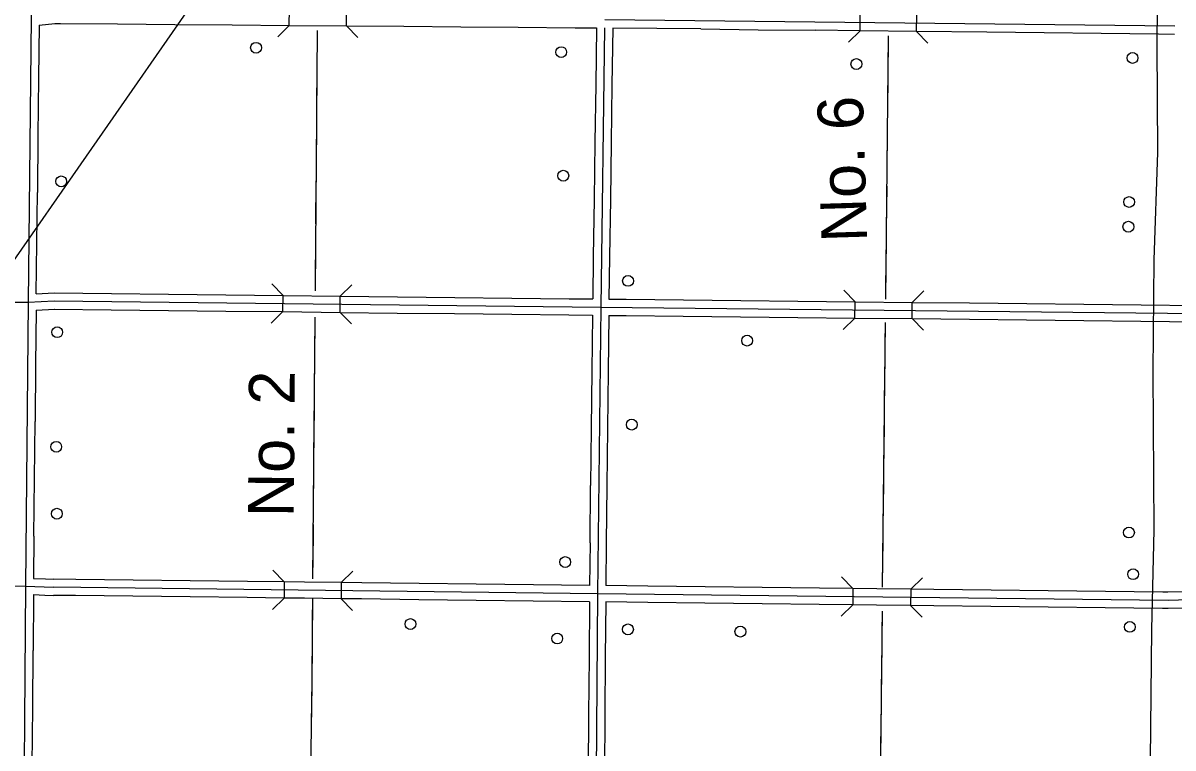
# Model space of a CAD drawing. Extents: x -4306 to 3843, y 131 to 8053.
# Drawn here: x -1949 to -251, y 879 to 1950 of the extents above; entities that cross this region are included whole.
import ezdxf

# ---------------------------------------------------------------- set-up
doc = ezdxf.new("R2010")
doc.units = 0
for name, color, linetype in [('10', 7, 'Continuous'), ('31', 7, 'Continuous'), ('32', 7, 'Continuous'), ('38', 7, 'Continuous'), ('43', 7, 'Continuous'), ('56', 7, 'Continuous'), ('R_No Plot', 7, 'Continuous')]:
    doc.layers.add(name, color=color, linetype=linetype)

msp = doc.modelspace()

# ---------------------------------------------------------------- linework, layer by layer
at = {"layer": '10'}
msp.add_lwpolyline([(-314.4, 293.8), (-314.5, 305.1), (-312.3, 441.3), (-305.4, 600.9), (-302, 628.3), (-293.8, 664.7), (-283.6, 735.2), (-284.1, 861.9), (-282.2, 1054.1), (-278.9, 1201.3), (-280.3, 1434.8), (-278.7, 1599.9), (-273.4, 1758.6), (-274.2, 1917.6), (-271, 2305.4), (-270.3, 2716.6), (-269.9, 2753.7)], dxfattribs=at)
at = {"layer": '31'}
for p, q in [((-713.1, 1938.1), (-712.8, 1962.1)), ((-629.6, 1937.2), (-629.3, 1961.2)), ((-948.3, 1940.8), (-1078.4, 1942.2)), ((-713.1, 1938.1), (-779.3, 1938.9)), ((-629.6, 1937.2), (-713.1, 1938.1)), ((-525.9, 1936), (-629.6, 1937.2)), ((-441.4, 1935.1), (-525.9, 1936)), ((-356.9, 1934.1), (-441.4, 1935.1)), ((-272.4, 1933.2), (-356.9, 1934.1)), ((-248.5, 1932.9), (-272.4, 1933.2)), ((-1926.5, 1868.2), (-1927.3, 1783.7)), ((-1927.3, 1783.7), (-1928.2, 1699.2)), ((-1929.7, 1549.9), (-1928.2, 1699.2)), ((-1928.2, 1699.2), (-1928.2, 1699.2)), ((-1930, 1525.9), (-1930.7, 1445.7)), ((-1930.7, 1445.7), (-1931.5, 1361.3)), ((-1931.5, 1361.3), (-1931.5, 1361.3)), ((-1933.2, 1192.3), (-1933.8, 1129.8)), ((-1934, 1105.8), (-1934.5, 1023.3))]:
    msp.add_line(p, q, dxfattribs=at)
for points in [[(-1925.7, 1946.5), (-1926.5, 1868.2)], [(-948.3, 1940.8), (-863.8, 1939.8)], [(-863.8, 1939.8), (-779.3, 1938.9)], [(-1932.4, 1276.8), (-1931.5, 1361.3)], [(-1933.2, 1192.3), (-1932.4, 1276.8)], [(-1935.1, 938.9), (-1934.5, 1023.3)], [(-1935.7, 854.4), (-1935.1, 938.9)]]:
    msp.add_lwpolyline(points, dxfattribs=at)
at = {"layer": '32'}
for p, q in [((-1556.1, 1946.2), (-1555.9, 1970.2)), ((-1471.6, 1945.5), (-1471.4, 1969.5)), ((-248.2, 1944.9), (-1090.3, 1954.4)), ((-1925.7, 1946.5), (-1902.6, 1949)), ((-1902.6, 1949), (-1894, 1948.9)), ((-1894, 1948.9), (-1809.6, 1948.3)), ((-1809.6, 1948.3), (-1725.1, 1947.6)), ((-1725.1, 1947.6), (-1640.6, 1946.9)), ((-1640.6, 1946.9), (-1556.1, 1946.2)), ((-1556.1, 1946.2), (-1471.6, 1945.5)), ((-1471.6, 1945.5), (-1387.1, 1944.8)), ((-1387.1, 1944.8), (-1302.6, 1944.1)), ((-1302.6, 1944.1), (-1218.2, 1943.4)), ((-1218.2, 1943.4), (-1133.7, 1942.7)), ((-1133.7, 1942.7), (-1102.6, 1942.5)), ((-1102.4, 1942.7), (-1103.6, 1858.2)), ((-1090.4, 1942.6), (-1096.1, 1530.1)), ((-1078.4, 1942.2), (-1079.6, 1857.9)), ((-1103.6, 1858.2), (-1104.8, 1773.8)), ((-1079.6, 1857.9), (-1080.8, 1773.4)), ((-1104.8, 1773.8), (-1105.9, 1689.3)), ((-1080.8, 1773.4), (-1081.9, 1688.9)), ((-1105.9, 1689.3), (-1107.1, 1604.8)), ((-1081.9, 1688.9), (-1083.1, 1604.5)), ((-1107.1, 1604.8), (-1108, 1542.2)), ((-1083.1, 1604.5), (-1084, 1542)), ((-1929.7, 1549.9), (-1903.6, 1551.4)), ((-1903.6, 1551.4), (-1818.7, 1550.4)), ((-1818.7, 1550.4), (-1734.3, 1549.4)), ((-1734.3, 1549.4), (-1649.8, 1548.4)), ((-1649.8, 1548.4), (-1565.3, 1547.5)), ((-1565.6, 1523.5), (-1565.3, 1547.5)), ((-1565.3, 1547.5), (-1480.8, 1546.5)), ((-1481.1, 1522.5), (-1480.8, 1546.5)), ((-1480.8, 1546.5), (-1396.3, 1545.5)), ((-2581.2, 1542), (-1941.9, 1537.3)), ((-1941.9, 1537.3), (-1903.4, 1539.3)), ((-1903.4, 1539.3), (-1096.1, 1530.1)), ((-1396.3, 1545.5), (-1311.8, 1544.6)), ((-1311.8, 1544.6), (-1227.4, 1543.6)), ((-1227.4, 1543.6), (-1142.9, 1542.6)), ((-1142.9, 1542.6), (-1108, 1542.2)), ((-1096.1, 1530.1), (-1100.7, 1107.1)), ((-1096.1, 1530.1), (156, 1516.7)), ((-1084, 1542), (-1058.4, 1541.7)), ((-1058.4, 1541.7), (-973.9, 1540.8)), ((-973.9, 1540.8), (-889.4, 1539.9)), ((-889.4, 1539.9), (-804.9, 1539)), ((-804.9, 1539), (-720.5, 1538.1)), ((-720.7, 1514.1), (-720.5, 1538.1)), ((-720.5, 1538.1), (-636, 1537.2)), ((-636.2, 1513.2), (-636, 1537.2)), ((-636, 1537.2), (-551.5, 1536.3)), ((-551.5, 1536.3), (-467, 1535.4)), ((-467, 1535.4), (-382.5, 1534.4)), ((-382.5, 1534.4), (-298, 1533.5)), ((-298, 1533.5), (-213.6, 1532.6)), ((-1930, 1525.9), (-1902.7, 1527.4)), ((-1903.5, 1527.3), (-1819, 1526.4)), ((-1819, 1526.4), (-1734.5, 1525.4)), ((-1734.5, 1525.4), (-1650, 1524.4)), ((-1650, 1524.4), (-1565.6, 1523.5)), ((-1565.6, 1523.5), (-1481.1, 1522.5)), ((-1481.1, 1522.5), (-1396.6, 1521.5)), ((-1396.6, 1521.5), (-1312.1, 1520.6)), ((-1312.1, 1520.6), (-1227.6, 1519.6)), ((-1227.6, 1519.6), (-1143.1, 1518.6)), ((-1143.1, 1518.6), (-1108.3, 1518.2)), ((-1108.3, 1518.2), (-1109.2, 1435.8)), ((-1084.3, 1518), (-1085.2, 1435.5)), ((-1084.3, 1518), (-1058.7, 1517.7)), ((-1058.7, 1517.7), (-974.2, 1516.8)), ((-974.2, 1516.8), (-889.7, 1515.9)), ((-889.7, 1515.9), (-805.2, 1515)), ((-805.2, 1515), (-720.7, 1514.1)), ((-720.7, 1514.1), (-636.2, 1513.2)), ((-636.2, 1513.2), (-551.7, 1512.3)), ((-551.7, 1512.3), (-467.3, 1511.4)), ((-467.3, 1511.4), (-382.8, 1510.4)), ((-382.8, 1510.4), (-298.3, 1509.5)), ((-298.3, 1509.5), (-213.8, 1508.6)), ((-1109.2, 1435.8), (-1110.1, 1351.3)), ((-1085.2, 1435.5), (-1086.1, 1351)), ((-1110.1, 1351.3), (-1111, 1266.8)), ((-1086.1, 1351), (-1087, 1266.6)), ((-1111.9, 1182.3), (-1111, 1266.8)), ((-1111.9, 1182.3), (-1111, 1266.8)), ((-1087, 1266.6), (-1087.9, 1182.1)), ((-1111.9, 1182.3), (-1112.6, 1119.3)), ((-1087.9, 1182.1), (-1088.6, 1119)), ((-2592.6, 1124.5), (-1945.9, 1118.2)), ((-1933.8, 1129.8), (-1916.3, 1129.2)), ((-1916.3, 1129.2), (-1903.7, 1128.7)), ((-1871.4, 1128.3), (-1904, 1128.7)), ((-1786.9, 1127.3), (-1871.4, 1128.3)), ((-1702.4, 1126.3), (-1786.9, 1127.3)), ((-1617.9, 1125.3), (-1702.4, 1126.3)), ((-1563.6, 1124.6), (-1617.9, 1125.3)), ((-1563.6, 1124.6), (-1563.9, 1100.6)), ((-1533.5, 1124.3), (-1563.7, 1124.6)), ((-1479.3, 1123.6), (-1533.5, 1124.3)), ((-1479.3, 1123.6), (-1479.6, 1099.6)), ((-1449, 1123.3), (-1479.3, 1123.6)), ((-1364.5, 1122.3), (-1449, 1123.3)), ((-1280, 1121.3), (-1364.5, 1122.3)), ((-1195.5, 1120.2), (-1280, 1121.3)), ((-1945.9, 1118.2), (-1904.1, 1116.7)), ((-1934, 1105.8), (-1917.1, 1105.2)), ((-1917.1, 1105.2), (-1904.5, 1104.7)), ((-1871.7, 1104.3), (-1904.3, 1104.7)), ((-1100.7, 1107.1), (-1904.1, 1116.7)), ((-1787.2, 1103.3), (-1871.7, 1104.3)), ((-1112.6, 1119.3), (-1195.5, 1120.2)), ((-1100.7, 1107.1), (-1107, 268.2)), ((-258.3, 1097.3), (-1100.7, 1107.1)), ((-1026.6, 1118.3), (-1088.6, 1119)), ((-942.1, 1117.3), (-1026.6, 1118.3)), ((-857.6, 1116.3), (-942.1, 1117.3)), ((-773.1, 1115.3), (-857.6, 1116.3)), ((-723.7, 1114.7), (-773.1, 1115.3)), ((-723.7, 1114.7), (-724, 1090.7)), ((-688.6, 1114.3), (-723.7, 1114.7)), ((-638.1, 1113.8), (-688.6, 1114.3)), ((-638.1, 1113.8), (-638.4, 1089.7)), ((-604.1, 1113.4), (-638.1, 1113.8)), ((-519.7, 1112.4), (-604.1, 1113.4)), ((-435.2, 1111.4), (-519.7, 1112.4)), ((-350.7, 1110.4), (-435.2, 1111.4)), ((-266.2, 1109.4), (-350.7, 1110.4)), ((-258.4, 1109.3), (-266.2, 1109.4)), ((-182.2, 1111.3), (-258.4, 1109.3)), ((152.6, 1107.8), (-258.3, 1097.3)), ((-1702.7, 1102.3), (-1787.2, 1103.3)), ((-1618.2, 1101.3), (-1702.7, 1102.3)), ((-1564, 1100.6), (-1618.2, 1101.3)), ((-1533.7, 1100.3), (-1564, 1100.6)), ((-1479.6, 1099.6), (-1533.7, 1100.3)), ((-1449.3, 1099.3), (-1479.6, 1099.6)), ((-1364.8, 1098.3), (-1449.3, 1099.3)), ((-1280.3, 1097.3), (-1364.8, 1098.3)), ((-1195.8, 1096.2), (-1280.3, 1097.3)), ((-1112.8, 1095.3), (-1195.8, 1096.2)), ((-1112.8, 1095.3), (-1113.4, 1013.3)), ((-1088.8, 1095), (-1089.4, 1013.2)), ((-1026.8, 1094.3), (-1088.8, 1095)), ((-942.4, 1093.3), (-1026.8, 1094.3)), ((-857.9, 1092.3), (-942.4, 1093.3)), ((-773.4, 1091.3), (-857.9, 1092.3)), ((-723.9, 1090.7), (-773.4, 1091.3)), ((-688.9, 1090.3), (-724, 1090.7)), ((-638.2, 1089.7), (-688.9, 1090.3)), ((-604.4, 1089.4), (-638.2, 1089.7)), ((-519.9, 1088.4), (-604.4, 1089.4)), ((-435.5, 1087.4), (-519.9, 1088.4)), ((-351, 1086.4), (-435.5, 1087.4)), ((-181.6, 1087.3), (-258.2, 1085.3)), ((-266.5, 1085.4), (-351, 1086.4)), ((-258.2, 1085.3), (-266.5, 1085.4)), ((-1113.4, 1013.3), (-1114.1, 928.8)), ((-1089.4, 1013.2), (-1090.1, 928.7)), ((-1114.1, 928.8), (-1114.7, 844.4)), ((-1090.1, 928.7), (-1090.7, 844.2))]:
    msp.add_line(p, q, dxfattribs=at)
msp.add_lwpolyline([(-1927.2, 3133.3), (-1928.9, 2805.9), (-1937.5, 1957.3), (-1941.9, 1537.3), (-1945.9, 1118.2), (-1949.1, 657.8)], dxfattribs=at)
at = {"layer": '38'}
for p, q in [((-723.9, 1102.8), (-723.9, 1102.8)), ((-638.2, 1101.8), (-638.2, 1101.8))]:
    msp.add_line(p, q, dxfattribs=at)
for points in [[(-1556.1, 1946.2), (-1573.2, 1929.3)], [(-1454.8, 1928.4), (-1471.6, 1945.5)], [(-713.1, 1938.1), (-730.2, 1921.3)], [(-612.8, 1920), (-629.6, 1937.2)], [(-1582.1, 1564.6), (-1565.3, 1547.5)], [(-1480.8, 1546.5), (-1463.6, 1563.3)], [(-737.3, 1555.2), (-720.5, 1538.1)], [(-636, 1537.2), (-618.8, 1554)], [(-1565.6, 1523.5), (-1582.7, 1506.7)], [(-1464.3, 1505.3), (-1481.1, 1522.5)], [(-720.7, 1514.1), (-737.9, 1497.3)], [(-619.4, 1496), (-636.2, 1513.2)], [(-1580.2, 1141.8), (-1563.5, 1124.6)], [(-1479.3, 1123.6), (-1462.1, 1140.4)], [(-723.7, 1114.8), (-740.5, 1132)], [(-620.9, 1130.6), (-638.1, 1113.8)], [(-1563.8, 1100.6), (-1580.9, 1083.9)], [(-1462.8, 1082.5), (-1479.6, 1099.6)], [(-741.2, 1074), (-724, 1090.8)], [(-638.4, 1089.8), (-621.6, 1072.6)]]:
    msp.add_lwpolyline(points, dxfattribs=at)
at = {"layer": '43'}
for points in [[(-1514.8, 1938.5), (-1518.1, 1554)], [(-1514.8, 1938.5), (-1515.1, 1906.8)], [(-671.4, 1930.7), (-675.6, 1542)], [(-671.4, 1930.7), (-671.8, 1899)], [(-1515.3, 1885.7), (-1515.8, 1822.3)], [(-672, 1877.9), (-672.7, 1814.5)], [(-1516, 1801.2), (-1516.5, 1737.8)], [(-672.9, 1793.4), (-673.6, 1730)], [(-1516.7, 1716.7), (-1517.2, 1653.3)], [(-673.8, 1708.9), (-674.5, 1645.5)], [(-1517.4, 1632.2), (-1517.9, 1568.9)], [(-674.7, 1624.4), (-675.4, 1561.1)], [(-1518.4, 1515.5), (-1521.6, 1129.1)], [(-1518.4, 1515.5), (-1518.6, 1483.8)], [(-676, 1507.4), (-680.3, 1117)], [(-676, 1507.4), (-676.4, 1475.7)], [(-1518.8, 1462.7), (-1519.3, 1399.3)], [(-676.6, 1454.6), (-677.3, 1391.2)], [(-1519.5, 1378.2), (-1520.1, 1314.9)], [(-677.5, 1370.1), (-678.2, 1306.7)], [(-1520.2, 1293.7), (-1520.8, 1230.4)], [(-678.4, 1285.6), (-679.1, 1222.3)], [(-1520.9, 1209.3), (-1521.5, 1145.9)], [(-679.3, 1201.1), (-680, 1137.8)], [(-1521.8, 1099.7), (-1522.9, 972), (-1533.2, 305.2)], [(-1521.8, 1099.7), (-1522.1, 1068)], [(-680.6, 1081.4), (-689.1, 300.9)], [(-680.6, 1081.4), (-681, 1049.7)], [(-1522.3, 1046.9), (-1522.8, 983.5)], [(-681.2, 1028.6), (-681.9, 965.2)], [(-1523.1, 962.4), (-1524, 899.1)], [(-682.1, 944.1), (-682.8, 880.8)]]:
    msp.add_lwpolyline(points, dxfattribs=at)
at = {"layer": '56'}
for centre in [(-1605.2, 1913.1), (-1154.5, 1906.6), (-310.7, 1898.1), (-718.6, 1889), (-1893, 1715.8), (-1151.4, 1724.2), (-315.7, 1685.4), (-316.8, 1648.9), (-1055.8, 1568.9), (-1898.9, 1493.2), (-879.9, 1480.7), (-1050.3, 1356.7), (-1900.3, 1324), (-1899.4, 1225.2), (-316, 1197.4), (-1148.6, 1153.9), (-309.8, 1135.9), (-1377.1, 1062.3), (-1055.9, 1054.5), (-889.9, 1051.1), (-314.7, 1058.1), (-1160.4, 1040.9)]:
    msp.add_circle(centre, 8, dxfattribs=at)
at = {"layer": 'R_No Plot'}
msp.add_line((-2436.2, 918.6), (-544.5, 3638.5), dxfattribs=at)

# ---------------------------------------------------------------- texts
at = {"layer": '43'}
for s, rotation, p in [('No. 6', 91.7362, (-702.5, 1626.9)), ('No. 2', 89.5125, (-1549.7, 1220))]:
    msp.add_text(s, height=67.59, rotation=rotation, dxfattribs=at).set_placement(p)

doc.saveas('drawing.dxf')
